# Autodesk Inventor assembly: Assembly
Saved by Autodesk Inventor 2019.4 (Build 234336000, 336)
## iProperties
Created: 2021-08
Part Number: Assembly
Document SubType Name: Assembly
Designer: Administrator
Title: Assembly v1
Author: Administrator
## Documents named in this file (19)
- c:\worker\convert-fusion-r06\tmp\job-1\20\output\files\f01db8e3-9ba6-469c-91a4-18b8ab1b818d\30520369-a497-4dbd-8c2e-b78a9a27c54f.iam
- c:\worker\convert-fusion-r06\tmp\job-1\20\output\files\f01db8e3-9ba6-469c-91a4-18b8ab1b818d\Faceplate v7.ipt
- c:\worker\convert-fusion-r06\tmp\job-1\20\output\files\f01db8e3-9ba6-469c-91a4-18b8ab1b818d\Base v12.ipt
- c:\worker\convert-fusion-r06\tmp\job-1\20\output\files\f01db8e3-9ba6-469c-91a4-18b8ab1b818d\Slider v9.ipt
- c:\worker\convert-fusion-r06\tmp\job-1\20\output\files\f01db8e3-9ba6-469c-91a4-18b8ab1b818d\Retainer v8.ipt
- c:\worker\convert-fusion-r06\tmp\job-1\20\output\files\f01db8e3-9ba6-469c-91a4-18b8ab1b818d\Guide v17.ipt
- c:\worker\convert-fusion-r06\tmp\job-1\20\output\files\f01db8e3-9ba6-469c-91a4-18b8ab1b818d\cylinder head screw DIN 912 M4x20 v4.iam
- c:\worker\convert-fusion-r06\tmp\job-1\20\output\files\f01db8e3-9ba6-469c-91a4-18b8ab1b818d\cylinder head screw DIN 912 M4x20 v4_1.iam
- c:\worker\convert-fusion-r06\tmp\job-1\20\output\files\f01db8e3-9ba6-469c-91a4-18b8ab1b818d\cylinder head screw DIN 912 M4x20 v4_2.iam
- c:\worker\convert-fusion-r06\tmp\job-1\20\output\files\f01db8e3-9ba6-469c-91a4-18b8ab1b818d\cylinder head screw DIN 912 M4x20 v4_3.iam
- c:\worker\convert-fusion-r06\tmp\job-1\20\output\files\f01db8e3-9ba6-469c-91a4-18b8ab1b818d\High knurled screw M3 (thread shortened) v6.iam
- c:\worker\convert-fusion-r06\tmp\job-1\20\output\files\f01db8e3-9ba6-469c-91a4-18b8ab1b818d\Flat knurled screw M4x10 v5.iam
- c:\worker\convert-fusion-r06\tmp\job-1\20\output\files\f01db8e3-9ba6-469c-91a4-18b8ab1b818d\Flat knurled screw M4x10 v5_1.iam
- c:\worker\convert-fusion-r06\tmp\job-1\20\output\files\f01db8e3-9ba6-469c-91a4-18b8ab1b818d\High knurled screw M5x12 v5.iam
- c:\worker\convert-fusion-r06\tmp\job-1\20\output\files\f01db8e3-9ba6-469c-91a4-18b8ab1b818d\High knurled screw M5x12 v5_1.iam
- c:\worker\convert-fusion-r06\tmp\job-1\20\output\files\f01db8e3-9ba6-469c-91a4-18b8ab1b818d\parallel pin ISO 8734 3m6x12 Blank.ipt
- c:\worker\convert-fusion-r06\tmp\job-1\20\output\files\f01db8e3-9ba6-469c-91a4-18b8ab1b818d\parallel pin ISO 8734 2m6x20 Blank.ipt
- c:\worker\convert-fusion-r06\tmp\job-1\20\output\files\f01db8e3-9ba6-469c-91a4-18b8ab1b818d\Spring plunger with thread locking  GN 615.3-M3-K-PFB .ipt
- c:\worker\convert-fusion-r06\tmp\job-1\20\output\files\f01db8e3-9ba6-469c-91a4-18b8ab1b818d\washer DIN 9021 6.4 A4 .ipt
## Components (19 placed, 13 different names)
1. Faceplate v7:1
2. Base v12:1
3. Slider v9:1
4. Retainer v8:1
5. Guide v17:1
6. cylinder head screw DIN 912 M4x20 v4:1 [sub-assembly]
7. cylinder head screw DIN 912 M4x20 v4:2 [sub-assembly]
8. cylinder head screw DIN 912 M4x20 v4:3 [sub-assembly]
9. cylinder head screw DIN 912 M4x20 v4:4 [sub-assembly]
10. High knurled screw M3 (thread shortened) v6:1 [sub-assembly]
11. Flat knurled screw M4x10 v5:1 [sub-assembly]
12. Flat knurled screw M4x10 v5:2 [sub-assembly]
13. High knurled screw M5x12 v5:2 [sub-assembly]
14. High knurled screw M5x12 v5:3 [sub-assembly]
15. parallel pin ISO 8734 3m6x12 Blank:1
16. parallel pin ISO 8734 2m6x20 Blank:1
17. Spring plunger with thread locking  GN 615.3-M3-K-PFB :1
18. washer DIN 9021 6.4 A4 :1
19. parallel pin ISO 8734 2m6x20 Blank:2
